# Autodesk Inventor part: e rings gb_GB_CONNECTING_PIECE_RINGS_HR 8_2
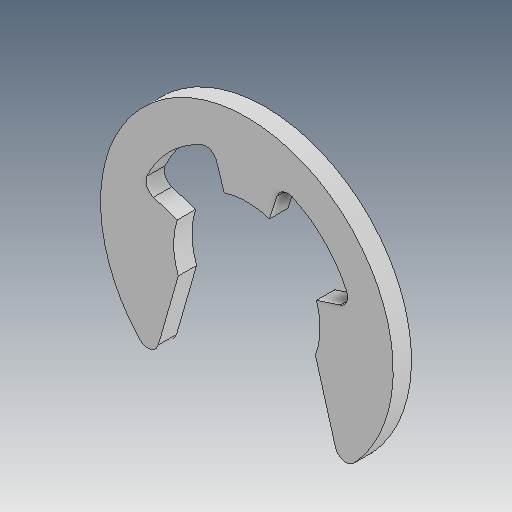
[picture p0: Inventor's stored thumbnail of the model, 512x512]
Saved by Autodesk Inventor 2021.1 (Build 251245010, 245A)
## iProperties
Created: 2019-04
Part Number: e rings gb_GB_CONNECTING_PIECE_RINGS_HR 8_2
Material: Ogólny
Document SubType Name: Modeling
Designer: user
Density: 1 g/cm^3
Appearance: Domyślna
Author: user
Revision Number: ÈÎºÎ
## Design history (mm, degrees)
feature "ÊäÈë1"
node "Bryła1"
